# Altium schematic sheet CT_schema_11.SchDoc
size 274 x 160 mm
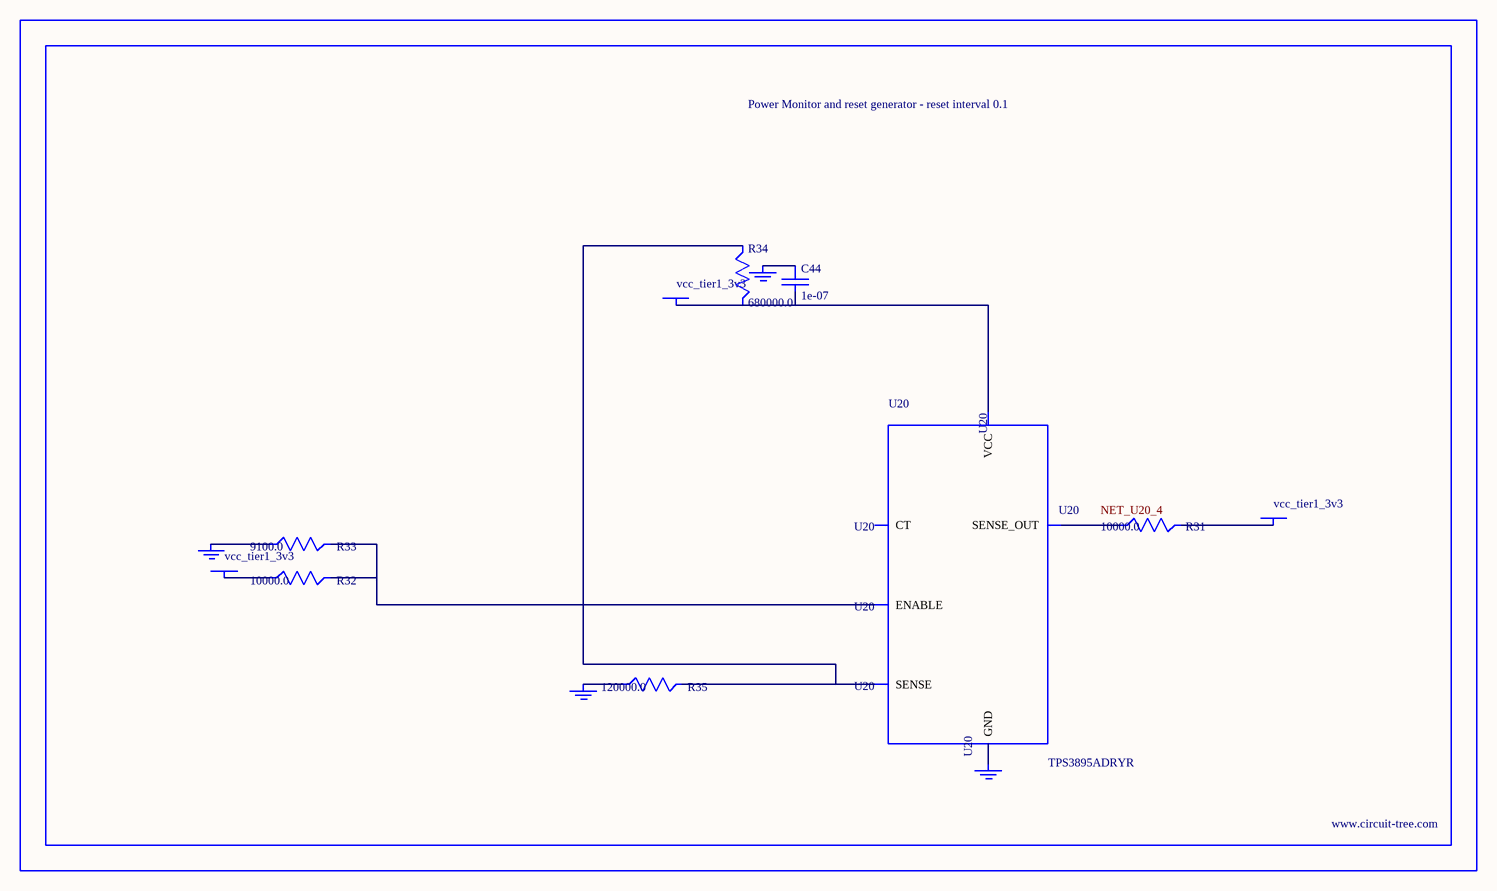
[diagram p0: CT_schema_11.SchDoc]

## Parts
BORDER10  (no value)
C44  1e-07  [C0402]
GND_INSTANCE_10_0  (no value)
GND_INSTANCE_10_1  (no value)
GND_INSTANCE_10_2  (no value)
GND_INSTANCE_10_3  (no value)
POWER_INSTANCE_10_0  vcc_tier1_3v3
POWER_INSTANCE_10_1  vcc_tier1_3v3
POWER_INSTANCE_10_2  vcc_tier1_3v3
R31  10000.0  [R0603]
R32  10000.0  [R0603]
R33  9100.0  [R0603]
R34  680000.0  [R0603]
R35  120000.0  [R0603]
U20  TPS3895ADRYR  [SON-6]

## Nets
NetC44_1: C44.1 GND_INSTANCE_10_2.0(GND)
NetC44_2: C44.2 POWER_INSTANCE_10_2.0(PWR) R34.2 U20.6(VCC)
NetGND_INSTANCE_10_0_0: GND_INSTANCE_10_0.0(GND) R33.1
NetGND_INSTANCE_10_1_0: GND_INSTANCE_10_1.0(GND) R35.1
NetGND_INSTANCE_10_3_0: GND_INSTANCE_10_3.0(GND) U20.2(GND)
NetPOWER_INSTANCE_10_0_0: POWER_INSTANCE_10_0.0(PWR) R32.1
NetPOWER_INSTANCE_10_1_0: POWER_INSTANCE_10_1.0(PWR) R31.2
NetR31_1: R31.1 U20.4(SENSE_OUT)
NetR32_2: R32.2 R33.2 U20.1(ENABLE)
NetR34_1: R34.1 R35.2 U20.3(SENSE)

Not connected (* = marked no-connect by the designer): U20 5(CT)

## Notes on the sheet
- Labels drawn without touching a wire or pin: NET_U20_4

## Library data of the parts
BORDER10 = BORDER_PAGE10
C44 = C0402C104K3RACTU
GND_INSTANCE_10_0-GND_INSTANCE_10_3 = GND
POWER_INSTANCE_10_0-POWER_INSTANCE_10_2 = PWR
R31 R32 = RC0603JR-0710KL
R33 = RC0603JR-079K1L
R34 = RC0603JR-07680KL
R35 = RC0603JR-07120KL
